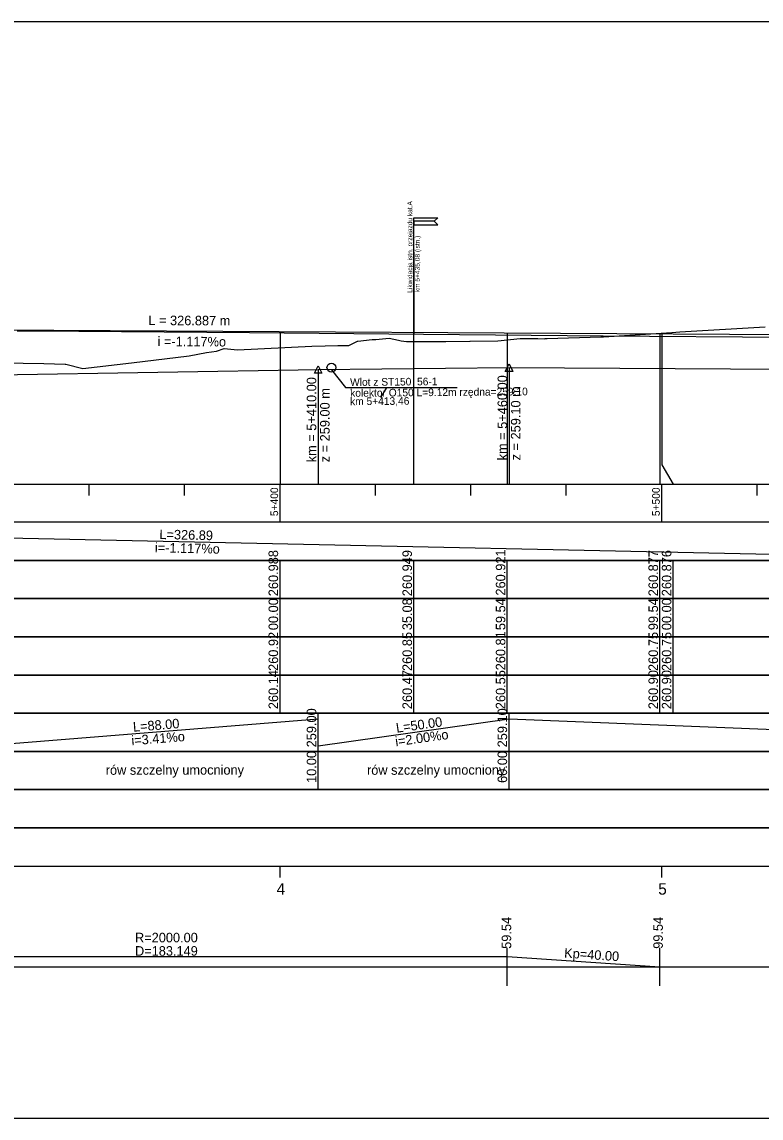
# Model space of a CAD drawing. Extents: x 6445630 to 6518227, y 5499240 to 5511716.
# Drawn here: x 6452463.6 to 6452657.3, y 5506120.7 to 5506407.7 of the extents above; entities that cross this region are included whole.
import ezdxf

# ---------------------------------------------------------------- set-up
doc = ezdxf.new("R2010")
doc.units = 0
for name, color, linetype in [('TOR_PROF-drenaze', 7, 'Continuous'), ('TOR_PROF-obiekty+opisy', 7, 'Continuous'), ('TOR_PROF-opisy pomocnicze', 7, 'Continuous'), ('TOR_PROF-rowy otwarte', 7, 'Continuous'), ('TOR_PROF-tabelka-geometria T1', 7, 'Continuous'), ('TOR_PROF-tabelka-kilometracja', 7, 'Continuous'), ('TOR_PROF-tabelka-odleglosci T1', 7, 'Continuous'), ('TOR_PROF-tabelka-pochylenia proj T1', 7, 'Continuous'), ('TOR_PROF-tabelka-rodzaj rowu T1', 7, 'Continuous'), ('TOR_PROF-tabelka-rowyT1', 7, 'Continuous'), ('TOR_PROF-tabelka-rzedne istn T1', 7, 'Continuous'), ('TOR_PROF-tabelka-rzedne proj T1', 7, 'Continuous'), ('TOR_PROF-tabelka-teren istniejacy T1', 7, 'Continuous'), ('TOR_PROF-tabelka-warstwa ochronna T1', 7, 'Continuous'), ('TOR_PROF-tor istniejacy T2', 7, 'Continuous'), ('TOR_PROF-tor projektowany', 7, 'Continuous'), ('TOR_PROF-uklad odniesienia', 7, 'Continuous'), ('TOR_PROF-warstwa ochronna', 7, 'Continuous'), ('TOR_RAMKI-dodatkowe3', 7, 'Continuous'), ('TOR_RAMKI-MASKA WYCIECIA', 7, 'Continuous')]:
    doc.layers.add(name, color=color, linetype=linetype)

msp = doc.modelspace()

# ---------------------------------------------------------------- linework, layer by layer
at = {"layer": 'TOR_PROF-obiekty+opisy'}
for p, q in [((6452566.29, 5506286.72), (6452566.29, 5506356.46)), ((6452566.29, 5506347.47), (6452566.29, 5506326)), ((6452544.66, 5506316.62), (6452548.35, 5506312.01)), ((6452548.35, 5506312.01), (6452577.61, 5506312.01)), ((6452559.02, 5506311.83), (6452557.54, 5506309.38))]:
    msp.add_line(p, q, dxfattribs=at)
for points in [[(6452572.54, 5506356.46), (6452571.61, 5506355.53), (6452566.29, 5506355.53), (6452566.29, 5506356.46), (6452572.54, 5506356.46)], [(6452572.54, 5506354.59), (6452571.61, 5506355.53), (6452566.29, 5506355.53), (6452566.29, 5506354.59), (6452572.54, 5506354.59)]]:
    msp.add_lwpolyline(points, dxfattribs=at)
msp.add_circle((6452544.69, 5506317.22), 1.17, dxfattribs=at)
at = {"layer": 'TOR_PROF-opisy pomocnicze'}
for p, q in [((6452541.21, 5506316.72), (6452541.21, 5506291.52)), ((6452591.21, 5506317.22), (6452591.21, 5506292.02))]:
    msp.add_line(p, q, dxfattribs=at)
for points in [[(6452541.21, 5506317.72), (6452542.21, 5506315.72), (6452540.21, 5506315.72)], [(6452591.21, 5506318.22), (6452592.21, 5506316.22), (6452590.21, 5506316.22)]]:
    msp.add_lwpolyline(points, close=True, dxfattribs=at)
at = {"layer": 'TOR_PROF-rowy otwarte'}
for p, q in [((6452453.21, 5506315.22), (6452541.21, 5506316.72)), ((6452541.21, 5506316.72), (6452591.21, 5506317.22)), ((6452591.21, 5506317.22), (6452767.21, 5506316.22))]:
    msp.add_line(p, q, dxfattribs=at)
for points in [[(6452541.21, 5506316.72), (6452541.21, 5506291.72), (6452541.21, 5506286.72), (6452541.21, 5506286.72)], [(6452591.21, 5506317.22), (6452591.21, 5506291.72), (6452591.21, 5506286.72), (6452591.21, 5506286.72)]]:
    msp.add_lwpolyline(points, dxfattribs=at)
at = {"layer": 'TOR_PROF-tabelka-geometria T1'}
for points in [[(6452341.21, 5506160.32), (6452367.61, 5506160.32), (6452367.61, 5506160.32), (6452407.61, 5506162.99), (6452407.61, 5506162.99), (6452590.75, 5506162.99), (6452590.75, 5506162.99), (6452630.75, 5506160.32), (6452630.75, 5506160.32), (6454509.94, 5506160.32), (6454509.94, 5506157.65), (6454551.51, 5506157.65), (6454551.51, 5506160.32), (6454558.69, 5506160.32), (6454558.69, 5506164.43), (6454600.28, 5506164.43)], [(6452590.75, 5506155.32), (6452590.75, 5506165.32)], [(6452630.75, 5506155.32), (6452630.75, 5506165.32)], [(6452331.21, 5506160.32), (6454631.21, 5506160.32)]]:
    msp.add_lwpolyline(points, dxfattribs=at)
at = {"layer": 'TOR_PROF-tabelka-kilometracja'}
for points in [[(6452531.21, 5506183.72), (6452531.21, 5506186.72)], [(6452631.21, 5506183.72), (6452631.21, 5506186.72)]]:
    msp.add_lwpolyline(points, dxfattribs=at)
at = {"layer": 'TOR_PROF-tabelka-odleglosci T1'}
msp.add_lwpolyline([(6452331.21, 5506246.72), (6454631.21, 5506246.72), (6454631.21, 5506256.72), (6452331.21, 5506256.72)], close=True, dxfattribs=at)
for points in [[(6452531.21, 5506246.72), (6452531.21, 5506256.72)], [(6452566.29, 5506246.72), (6452566.29, 5506256.72)], [(6452590.75, 5506246.72), (6452590.75, 5506256.72)], [(6452630.75, 5506246.72), (6452630.75, 5506256.72)], [(6452634.25, 5506246.72), (6452634.25, 5506256.72)]]:
    msp.add_lwpolyline(points, dxfattribs=at)
at = {"layer": 'TOR_PROF-tabelka-pochylenia proj T1'}
msp.add_lwpolyline([(6452331.21, 5506266.72), (6454631.21, 5506266.72), (6454631.21, 5506276.72), (6452331.21, 5506276.72)], close=True, dxfattribs=at)
msp.add_lwpolyline([(6452341.21, 5506275.22), (6452668.1, 5506268.22)], dxfattribs=at)
at = {"layer": 'TOR_PROF-tabelka-rodzaj rowu T1'}
msp.add_lwpolyline([(6452331.21, 5506206.72), (6454631.21, 5506206.72), (6454631.21, 5506216.72), (6452331.21, 5506216.72)], close=True, dxfattribs=at)
for points in [[(6452541.21, 5506206.72), (6452541.21, 5506216.72)], [(6452591.21, 5506206.72), (6452591.21, 5506216.72)]]:
    msp.add_lwpolyline(points, dxfattribs=at)
at = {"layer": 'TOR_PROF-tabelka-rowyT1'}
msp.add_lwpolyline([(6452331.21, 5506216.72), (6454631.21, 5506216.72), (6454631.21, 5506226.72), (6452331.21, 5506226.72)], close=True, dxfattribs=at)
for points in [[(6452453.21, 5506218.22), (6452541.21, 5506225.22)], [(6452541.21, 5506216.72), (6452541.21, 5506226.72)], [(6452541.21, 5506218.22), (6452591.21, 5506225.22)], [(6452591.21, 5506216.72), (6452591.21, 5506226.72)], [(6452591.21, 5506225.22), (6452767.21, 5506218.22)]]:
    msp.add_lwpolyline(points, dxfattribs=at)
at = {"layer": 'TOR_PROF-tabelka-rzedne istn T1'}
msp.add_lwpolyline([(6452331.21, 5506236.72), (6454631.21, 5506236.72), (6454631.21, 5506246.72), (6452331.21, 5506246.72)], close=True, dxfattribs=at)
for points in [[(6452531.21, 5506236.72), (6452531.21, 5506246.72)], [(6452566.29, 5506236.72), (6452566.29, 5506246.72)], [(6452590.75, 5506236.72), (6452590.75, 5506246.72)], [(6452630.75, 5506236.72), (6452630.75, 5506246.72)], [(6452634.25, 5506236.72), (6452634.25, 5506246.72)], [(6452531.21, 5506226.72), (6452531.21, 5506236.72)], [(6452566.29, 5506226.72), (6452566.29, 5506236.72)], [(6452590.75, 5506226.72), (6452590.75, 5506236.72)], [(6452630.75, 5506226.72), (6452630.75, 5506236.72)], [(6452634.25, 5506226.72), (6452634.25, 5506236.72)]]:
    msp.add_lwpolyline(points, dxfattribs=at)
at = {"layer": 'TOR_PROF-tabelka-rzedne proj T1'}
msp.add_lwpolyline([(6452331.21, 5506256.72), (6454631.21, 5506256.72), (6454631.21, 5506266.72), (6452331.21, 5506266.72)], close=True, dxfattribs=at)
for points in [[(6452531.21, 5506256.72), (6452531.21, 5506266.72)], [(6452566.29, 5506256.72), (6452566.29, 5506266.72)], [(6452590.75, 5506256.72), (6452590.75, 5506266.72)], [(6452630.75, 5506256.72), (6452630.75, 5506266.72)], [(6452634.25, 5506256.72), (6452634.25, 5506266.72)]]:
    msp.add_lwpolyline(points, dxfattribs=at)
at = {"layer": 'TOR_PROF-tabelka-teren istniejacy T1'}
msp.add_lwpolyline([(6452331.21, 5506226.72), (6454631.21, 5506226.72), (6454631.21, 5506236.72), (6452331.21, 5506236.72)], close=True, dxfattribs=at)
at = {"layer": 'TOR_PROF-tabelka-warstwa ochronna T1'}
msp.add_lwpolyline([(6452331.21, 5506196.72), (6454631.21, 5506196.72), (6454631.21, 5506206.72), (6452331.21, 5506206.72)], close=True, dxfattribs=at)
at = {"layer": 'TOR_PROF-tor istniejacy T2'}
msp.add_lwpolyline([(6452462.33, 5506326.83), (6452464.81, 5506326.83), (6452467.28, 5506326.82), (6452523.18, 5506326.37), (6452568.78, 5506325.97), (6452615.85, 5506325.57), (6452664.56, 5506325.22)], dxfattribs=at)
at = {"layer": 'TOR_PROF-tor projektowany'}
msp.add_line((6452341.21, 5506327.72), (6452668.1, 5506325.9), dxfattribs=at)
msp.add_line((6452341.21, 5506327.72), (6452668.1, 5506325.9), dxfattribs=at)
for points in [[(6452531.21, 5506326.66), (6452531.21, 5506291.72), (6452531.21, 5506286.72), (6452531.21, 5506286.72)], [(6452531.21, 5506326.66), (6452531.21, 5506291.72), (6452531.21, 5506286.72), (6452531.21, 5506286.72)], [(6452590.75, 5506326.33), (6452590.75, 5506291.72), (6452590.75, 5506286.72), (6452590.75, 5506286.72)], [(6452590.75, 5506326.33), (6452590.75, 5506291.72), (6452590.75, 5506286.72), (6452590.75, 5506286.72)], [(6452630.75, 5506326.11), (6452630.75, 5506291.72), (6452630.75, 5506286.72), (6452630.75, 5506286.72)], [(6452630.75, 5506326.11), (6452630.75, 5506291.72), (6452630.75, 5506286.72), (6452630.75, 5506286.72)], [(6452631.21, 5506326.11), (6452631.21, 5506291.72), (6452634.25, 5506286.72), (6452634.25, 5506286.72)], [(6452631.21, 5506326.11), (6452631.21, 5506291.72), (6452634.25, 5506286.72), (6452634.25, 5506286.72)]]:
    msp.add_lwpolyline(points, dxfattribs=at)
at = {"layer": 'TOR_PROF-uklad odniesienia'}
for p, q in [((6452331.21, 5506286.72), (6454631.21, 5506286.72)), ((6452481.21, 5506283.72), (6452481.21, 5506286.72)), ((6452506.21, 5506283.72), (6452506.21, 5506286.72)), ((6452531.21, 5506276.72), (6452531.21, 5506286.72)), ((6452556.21, 5506283.72), (6452556.21, 5506286.72)), ((6452581.21, 5506283.72), (6452581.21, 5506286.72)), ((6452606.21, 5506283.72), (6452606.21, 5506286.72)), ((6452631.21, 5506276.72), (6452631.21, 5506286.72)), ((6452656.21, 5506283.72), (6452656.21, 5506286.72))]:
    msp.add_line(p, q, dxfattribs=at)
at = {"layer": 'TOR_PROF-warstwa ochronna'}
msp.add_lwpolyline([(6452331.21, 5506186.72), (6454631.21, 5506186.72), (6454631.21, 5506196.72), (6452331.21, 5506196.72)], close=True, dxfattribs=at)
at = {"layer": 'TOR_RAMKI-dodatkowe3'}
for p, q in [((6452636, 5506326.54), (6452658.29, 5506327.87)), ((6452551.62, 5506324.16), (6452555.35, 5506324.6)), ((6452555.35, 5506324.6), (6452556.32, 5506324.59)), ((6452556.32, 5506324.59), (6452559.82, 5506324.9)), ((6452559.82, 5506324.9), (6452562.25, 5506324.36)), ((6452588.24, 5506324.23), (6452594.17, 5506324.81)), ((6452594.17, 5506324.81), (6452598.72, 5506324.83)), ((6452598.72, 5506324.83), (6452600.44, 5506324.79)), ((6452600.44, 5506324.79), (6452600.64, 5506324.82)), ((6452600.64, 5506324.82), (6452601.24, 5506324.82)), ((6452601.24, 5506324.82), (6452615.28, 5506325.25)), ((6452615.28, 5506325.25), (6452616, 5506325.29)), ((6452616, 5506325.29), (6452633.87, 5506326.41)), ((6452633.87, 5506326.41), (6452636, 5506326.54)), ((6452514.58, 5506321.5), (6452516.57, 5506322.22)), ((6452516.57, 5506322.22), (6452520.11, 5506321.88)), ((6452520.11, 5506321.88), (6452539.52, 5506322.84)), ((6452539.52, 5506322.84), (6452543.03, 5506322.94)), ((6452543.03, 5506322.94), (6452546.33, 5506323.04)), ((6452546.33, 5506323.04), (6452549.2, 5506323)), ((6452549.2, 5506323), (6452550.33, 5506323.52)), ((6452550.33, 5506323.52), (6452551.53, 5506324.1)), ((6452551.53, 5506324.1), (6452551.56, 5506324.12)), ((6452551.56, 5506324.12), (6452551.62, 5506324.16)), ((6452562.25, 5506324.36), (6452562.92, 5506324.26)), ((6452562.92, 5506324.26), (6452564.35, 5506324.06)), ((6452564.35, 5506324.06), (6452574.44, 5506324.07)), ((6452574.44, 5506324.07), (6452574.67, 5506324.02)), ((6452574.67, 5506324.02), (6452580.96, 5506324.16)), ((6452580.96, 5506324.16), (6452581.03, 5506324.16)), ((6452581.03, 5506324.16), (6452588.24, 5506324.23)), ((6452492.33, 5506318.44), (6452507.45, 5506320.33)), ((6452507.45, 5506320.33), (6452511.95, 5506321.21)), ((6452511.95, 5506321.21), (6452514.58, 5506321.5)), ((6452458.46, 5506318.5), (6452469.36, 5506318.27)), ((6452469.36, 5506318.27), (6452474.9, 5506318.13)), ((6452474.9, 5506318.13), (6452475.07, 5506318.11)), ((6452475.07, 5506318.11), (6452479.55, 5506316.99)), ((6452479.55, 5506316.99), (6452492.33, 5506318.44))]:
    msp.add_line(p, q, dxfattribs=at)
at = {"layer": 'TOR_RAMKI-MASKA WYCIECIA'}
msp.add_lwpolyline([(6452265.31, 5506120.72), (6453965.31, 5506120.72), (6453965.31, 5506407.72), (6452265.31, 5506407.72)], close=True, dxfattribs=at)

# ---------------------------------------------------------------- texts
at = {"layer": 'TOR_PROF-drenaze'}
for s, p in [('Wlot z ST150_56-1', (6452549.58, 5506312.41)), ('kolektor O150 L=9.12m rzędna=259.10', (6452549.6, 5506309.57)), ('km 5+413,46', (6452549.58, 5506307.37))]:
    msp.add_text(s, height=2, rotation=0.4945, dxfattribs=at).set_placement(p)
at = {"layer": 'TOR_PROF-obiekty+opisy'}
for s, p in [('Likwidacja istn. przejazdu kat.A', (6452565.86, 5506336.82)), ('km 5+435,08 (istn.)', (6452567.82, 5506336.95))]:
    msp.add_text(s, height=1.25, rotation=90, dxfattribs=at).set_placement(p)
at = {"layer": 'TOR_PROF-opisy pomocnicze'}
for s, rotation, p in [('L = 326.887 m', 359.6801, (6452496.72, 5506328.36)), ('L = 326.887 m', 359.6801, (6452496.72, 5506328.36)), ('  i =-1.117%o', 359.6801, (6452497.27, 5506322.85)), ('  i =-1.117%o', 359.6801, (6452497.27, 5506322.85)), ('km = 5+410.00', 90, (6452540.71, 5506292.42)), ('km = 5+460.00', 90, (6452590.71, 5506292.92)), ('z = 259.00 m', 90, (6452544.21, 5506292.42)), ('z = 259.10 m', 90, (6452594.21, 5506292.92)), ('59.54', 90, (6452591.78, 5506165.04)), ('99.54', 90, (6452631.51, 5506165.04))]:
    msp.add_text(s, height=2.5, rotation=rotation, dxfattribs=at).set_placement(p)
at = {"layer": 'TOR_PROF-tabelka-geometria T1'}
for s, p in [('R=2000.00', (6452493.22, 5506166.74)), ('D=183.149', (6452493.22, 5506163.24))]:
    msp.add_text(s, height=2.5, dxfattribs=at).set_placement(p)
msp.add_text('Kp=40.00', height=2.5, rotation=356.1859, dxfattribs=at).set_placement((6452605.6, 5506162.75))
at = {"layer": 'TOR_PROF-tabelka-kilometracja'}
for s, p in [('4', (6452530.32, 5506179.22)), ('5', (6452630.31, 5506179.22))]:
    msp.add_text(s, height=3, dxfattribs=at).set_placement(p)
at = {"layer": 'TOR_PROF-tabelka-odleglosci T1'}
for s, p in [('00.00', (6452530.71, 5506248.47)), ('35.08', (6452565.79, 5506248.46)), ('59.54', (6452590.25, 5506248.47)), ('99.54', (6452630.25, 5506248.47)), ('00.00', (6452633.75, 5506248.47))]:
    msp.add_text(s, height=2.5, rotation=90, dxfattribs=at).set_placement(p)
at = {"layer": 'TOR_PROF-tabelka-pochylenia proj T1'}
for s, p in [('L=326.89', (6452499.59, 5506272.33)), ('i=-1.117%o', (6452498.41, 5506268.86))]:
    msp.add_text(s, height=2.5, rotation=358.7732, dxfattribs=at).set_placement(p)
at = {"layer": 'TOR_PROF-tabelka-rodzaj rowu T1'}
for s, p in [('10.00', (6452540.71, 5506208.47)), ('60.00', (6452590.71, 5506208.47))]:
    msp.add_text(s, height=2.5, rotation=90, dxfattribs=at).set_placement(p)
at = {"layer": 'TOR_PROF-tabelka-rowyT1'}
for s, rotation, p in [('259.00', 90, (6452540.71, 5506217.79)), ('259.10', 90, (6452590.71, 5506217.79)), ('L=88.00', 4.548, (6452492.79, 5506221.87)), ('L=50.00', 7.9696, (6452561.79, 5506221.61)), ('i=3.41%o', 4.548, (6452492.37, 5506218.33)), ('i=2.00%o', 7.9696, (6452561.58, 5506218.05)), ('rów szczelny umocniony', 0.087, (6452485.55, 5506210.6)), ('rów szczelny umocniony', 0.087, (6452554, 5506210.6))]:
    msp.add_text(s, height=2.5, rotation=rotation, dxfattribs=at).set_placement(p)
at = {"layer": 'TOR_PROF-tabelka-rzedne istn T1'}
for s, p in [('260.92', (6452530.71, 5506237.8)), ('260.85', (6452565.79, 5506237.78)), ('260.81', (6452590.25, 5506237.96)), ('260.75', (6452630.25, 5506237.78)), ('260.75', (6452633.75, 5506237.78)), ('260.14', (6452530.71, 5506227.79)), ('260.47', (6452565.79, 5506227.79)), ('260.55', (6452590.25, 5506227.78)), ('260.90', (6452630.25, 5506227.79)), ('260.90', (6452633.75, 5506227.79))]:
    msp.add_text(s, height=2.5, rotation=90, dxfattribs=at).set_placement(p)
at = {"layer": 'TOR_PROF-tabelka-rzedne proj T1'}
for s, p in [('260.988', (6452530.71, 5506257.36)), ('260.949', (6452565.79, 5506257.36)), ('260.921', (6452590.25, 5506257.53)), ('260.877', (6452630.25, 5506257.36)), ('260.876', (6452633.75, 5506257.36))]:
    msp.add_text(s, height=2.5, rotation=90, dxfattribs=at).set_placement(p)
at = {"layer": 'TOR_PROF-uklad odniesienia'}
for s, p in [('5+400', (6452530.71, 5506278.33)), ('5+500', (6452630.71, 5506278.33))]:
    msp.add_text(s, height=2, rotation=90, dxfattribs=at).set_placement(p)

doc.saveas('drawing.dxf')
